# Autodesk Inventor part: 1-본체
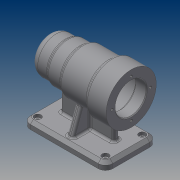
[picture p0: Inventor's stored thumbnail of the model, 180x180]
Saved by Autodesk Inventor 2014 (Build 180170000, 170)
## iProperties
Created: 2016-06
Part Number: 1-본체
Material: 일반
Document SubType Name: Modeling
Designer: SEC
Density: 1 g/cm^3
Appearance: 기본값
Author: SEC
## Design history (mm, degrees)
sketch "스케치1"
  geometry: L1 (-56, 0)-(56, 0); L2 (56, 21)-(56, 34); L3 (56, 34)-(28, 34); L4 (28, 34)-(28, 30); L5 (28, 30)-(-11, 30); L6 (-11, 30)-(-11, 27); L7 (-11, 27)-(-31, 27); L8 (-31, 27)-(-31, 25); L9 (-31, 25)-(-56, 25); L10 (-56, 25)-(-56, 0); L11 (56, 21)-(41, 21); L12 (41, 21)-(41, 24); L13 (41, 24)-(-13, 24); L14 (-13, 24)-(-13, 21); L15 (-13, 21)-(-25, 21); L16 (-25, 21)-(-25, 17.5); L17 (-25, 17.5)-(-43, 17.5); L18 (-43, 17.5)-(-43, 16); L19 (-43, 16)-(-47, 16); L20 (-47, 16)-(-47, 10.5); L21 (-47, 10.5)-(-50, 10.5); L22 (-50, 10.5)-(-50, 0); 2 further points
  constraints: 44 end point, 12 parallel, 9 perpendicular, 1 coincident, 1 horizontal, 1 midpoint, 1 point on line, 1 vertical alignment
  dimensions: "d0" = 112 distance of L1.start L1.end; "d1" = 68 diameter of L3 L1; "d2" = 50 diameter of L9 L1; "d3" = 54 diameter of L7 L1; "d4" = 60 diameter of L5 L1; "d5" = 84 horizontal distance of L3.end L9.end; "d6" = 45 horizontal distance of L9.end L5.end; "d7" = 25 horizontal distance of L9.end L7.end; "d9" = 42 diameter of L11 L1; "d10" = 48 diameter of L13 L1; "d11" = 42 diameter of L15 L1; "d12" = 35 diameter of L17 L1; "d13" = 32 diameter of L19 L1; "d14" = 21 diameter of L21 L1; "d15" = 15 distance of L2.start L11.end; "d16" = 54 distance of L12.end L13.end; "d17" = 12 distance of L14.end L15.end; "d18" = 18 distance of L16.end L17.end; "d19" = 4 distance of L18.end L19.end; "d20" = 3 distance of L20.end L21.end
revolve "회전1" sketch "스케치1" stored, may be unused: angle "d8" = 90 deg
node "작업 평면1"
sketch "스케치2"
  geometry: L1 (56, -35)-(-56, -35); L2 (-56, -35)-(-56, 35); L3 (-56, 35)-(56, 35); L4 (56, 35)-(56, -35); L5 (56, -35)-(-56, 35); L6 (-56, -35)-(56, 35); 1 further point
  constraints: 12 end point, 2 midpoint, 2 parallel, 1 horizontal, 1 perpendicular
  dimensions: "d22" = 112 distance of L2.end L3.end; "d23" = 70 distance of L3.end L1.start
extrude "돌출1" join sketch "스케치2" distance "d24" = 10; taper "d25" = 0 deg
node "작업 평면4"
node "작업 평면5"
sketch "스케치10"
  geometry: 2 further points
  constraints: 1 vertical alignment
  dimensions: "d54" = 26 distance of point (0, 26) point (0, 0)
hole "구멍1" sketch "스케치10" at (0, 26) diameter "d55" = 3.242; stored, may be unused: countersink angle "d59" = 90 deg, drill point angle "d61" = 118 deg; dims "d56" = 8, "d57" = 4, "d58" = 2, "d60" = 10
fillet "모깎기1" dims "d65" = 10
sketch "스케치12"
  geometry: 2 further points
  dimensions: "d67" = 46 horizontal distance of point (-46, 25) point (0, 0); "d68" = 25 vertical distance of point (-46, 25) point (0, 0)
hole "구멍2" sketch "스케치12" at (-46, 25) diameter "d69" = 5; stored, may be unused: countersink angle "d73" = 90 deg, drill point angle "d75" = 0 deg; dims "d70" = 8, "d71" = 9, "d72" = 4, "d74" = 10
fillet "모깎기2" dims "d89" = 0.3
fillet "모깎기3" dims "d90" = 3
fillet "모깎기6" dims "d93" = 10
chamfer "모따기2" distance "d94" = 1; stored, may be unused: second distance "d95" = 2, angle "d96" = 45 deg
chamfer "모따기3" distance "d98" = 4; stored, may be unused: second distance "d99" = 2, angle "d100" = 45 deg
node "작업 평면9"
sketch "스케치15"
  geometry: L1 (0, 10)-(50, 10) reference; L2 (9.491, 44.32)-(-3, 10); L3 (40.509, 44.32)-(53, 10); L4 (60, 6)-(60, 0) reference; L5 (-10, 0)-(-10, 6) reference; L6 (-3, 10)-(53, 10); A1 r 30 centre (25, 70) between (9.491, 44.32) and (40.509, 44.32) reference; 1 further point
  constraints: 6 end point, 2 point on circle, 2 point on line, 1 collinear
  dimensions: "d103" = 110 deg angle of L1 L3; "d104" = 7 distance from line of L3.end L4; "d105" = 110 deg angle of L1 L2; "d106" = 7 distance from line of L2.end L5
extrude "돌출4" join sketch "스케치15" stored distance "d107" = 8; taper "d108" = 0 deg
node "작업 평면10"
sketch "스케치16"
  geometry: L1 (18, 36)-(-10, 36) reference; L2 (0, 10)-(92, 10) reference; L3 (10, 10)-(10, 36); L4 (-10, 0)-(-10, 6) reference; 1 further point
  constraints: 2 end point, 2 point on line, 1 perpendicular
  dimensions: "d109" = 20 distance between parallel lines of L4 L3
feature "리브3" sketch "스케치16" dims "d110" = 1, "d111" = 8, "d112" = 0, "d113" = 0, "d114" = 1, "d115" = 1
sketch "스케치17"
  geometry: L1 (92, 45)-(77, 45) reference; L2 (0, 10)-(92, 10) reference; L3 (82, 10)-(82, 45); L4 (102, 6)-(102, 0) reference; 1 further point
  constraints: 2 end point, 2 point on line, 1 perpendicular
  dimensions: "d116" = 20 distance between parallel lines of L3 L4
feature "리브4" sketch "스케치17" dims "d117" = 1, "d118" = 8, "d119" = 0, "d120" = 0, "d121" = 1, "d122" = 1
fillet "모깎기10" dims "d123" = 3
fillet "모깎기11" dims "d124" = 3
fillet "모깎기12" dims "d125" = 3
fillet "모깎기13" dims "d126" = 3
fillet "모깎기14" dims "d127" = 3
node "솔리드1"
pattern_circular "원형 패턴1" dims angle "d63" = 360 deg
pattern_linear "직사각형 패턴1" dims "d78" = 92
